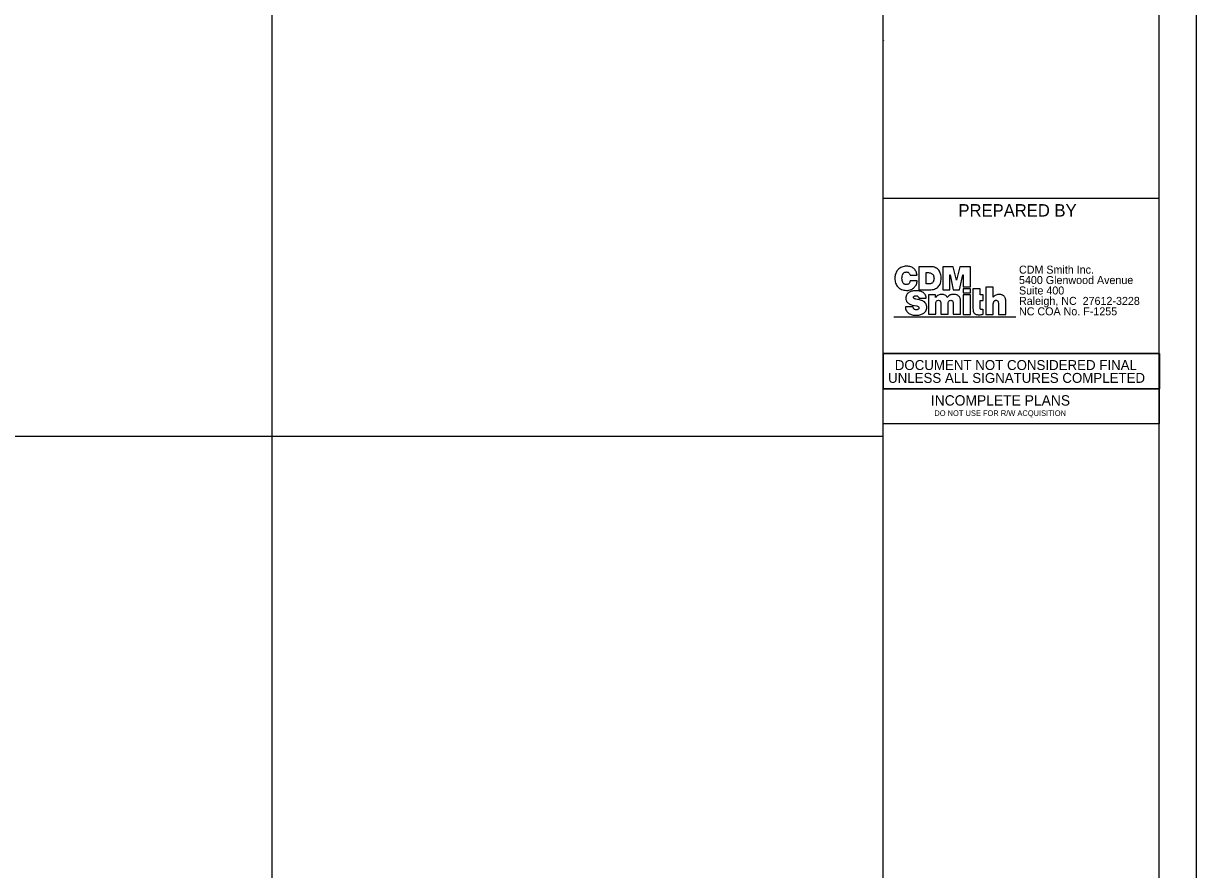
# Model space of a CAD drawing. Extents: x 0 to 1700, y -103 to 1100.
# Drawn here: x 1275 to 1700, y 498.6 to 805 of the extents above; entities that cross this region are included whole.
import ezdxf

# ---------------------------------------------------------------- set-up
doc = ezdxf.new("R2010")
doc.units = 0
for name, color, linetype in [('Default', 7, 'Continuous'), ('Level 17', 7, 'Continuous'), ('Sheet Block Title CELL', 7, 'Continuous'), ('Sheet Plan CELL', 7, 'Continuous'), ('Sheet_Plan_CELL', 7, 'Continuous')]:
    doc.layers.add(name, color=color, linetype=linetype)

msp = doc.modelspace()

# ---------------------------------------------------------------- linework, layer by layer
at = {"layer": 'Default'}
for p, q in [((1365, 1077.5), (1365, 22.52)), ((36.48, 655.5), (1586.48, 655.5))]:
    msp.add_line(p, q, dxfattribs=at)
at = {"layer": 'Level 17'}
msp.add_line((1699.98, 0.02), (1699.98, 1100), dxfattribs=at)
at = {"layer": 'Sheet Block Title CELL'}
msp.add_line((1590.33, 698.72), (1634.49, 698.71), dxfattribs=at)
for points in [[(1593.6, 711.17), (1593.52, 711.34), (1593.46, 711.51), (1593.34, 711.9), (1593.29, 712.3), (1593.26, 712.73), (1593.29, 713.15), (1593.34, 713.55), (1593.46, 713.95), (1593.52, 714.12), (1593.6, 714.29), (1593.71, 714.46), (1593.83, 714.6), (1593.94, 714.72), (1594.11, 714.83), (1594.25, 714.92), (1594.45, 714.97), (1594.65, 715), (1594.85, 715.03), (1595.05, 715), (1595.22, 714.97), (1595.36, 714.94), (1595.5, 714.89), (1595.65, 714.8), (1595.73, 714.72), (1595.9, 714.52), (1596.04, 714.32), (1596.13, 714.12), (1596.19, 713.92), (1596.21, 713.81), (1598.72, 713.81), (1598.66, 714.18), (1598.57, 714.55), (1598.49, 714.89), (1598.35, 715.2), (1598.2, 715.48), (1598.03, 715.77), (1597.83, 716.02), (1597.61, 716.22), (1597.35, 716.42), (1597.07, 716.62), (1596.78, 716.76), (1596.47, 716.88), (1596.1, 716.99), (1595.73, 717.05), (1595.33, 717.1), (1594.94, 717.1), (1594.45, 717.1), (1594, 717.02), (1593.57, 716.93), (1593.17, 716.79), (1592.81, 716.62), (1592.46, 716.42), (1592.12, 716.17), (1591.84, 715.91), (1591.58, 715.6), (1591.36, 715.29), (1591.16, 714.92), (1590.99, 714.52), (1590.84, 714.12), (1590.76, 713.67), (1590.7, 713.21), (1590.67, 712.73), (1590.7, 712.27), (1590.76, 711.82), (1590.84, 711.39), (1590.96, 711), (1591.13, 710.63), (1591.3, 710.26), (1591.53, 709.92), (1591.78, 709.6), (1592.07, 709.32), (1592.41, 709.09), (1592.75, 708.86), (1593.12, 708.69), (1593.52, 708.55), (1593.97, 708.44), (1594.42, 708.38), (1594.94, 708.35), (1595.36, 708.35), (1595.79, 708.44), (1596.19, 708.52), (1596.56, 708.67), (1596.9, 708.81), (1597.21, 709.01), (1597.49, 709.2), (1597.75, 709.46), (1597.98, 709.72), (1598.18, 709.97), (1598.35, 710.28), (1598.49, 710.57), (1598.6, 710.88), (1598.69, 711.19), (1598.74, 711.51), (1598.74, 711.82), (1596.21, 711.82), (1596.16, 711.53), (1596.07, 711.28), (1595.96, 711.05), (1595.82, 710.82), (1595.62, 710.65), (1595.42, 710.54), (1595.16, 710.46), (1594.85, 710.43), (1594.65, 710.46), (1594.45, 710.48), (1594.25, 710.54), (1594.11, 710.63), (1593.94, 710.74), (1593.83, 710.85), (1593.71, 711), (1593.6, 711.17)], [(1607.44, 712.27), (1607.44, 712.73), (1607.44, 713.13), (1607.41, 713.52), (1607.32, 713.92), (1607.24, 714.29), (1607.13, 714.63), (1606.98, 715), (1606.81, 715.31), (1606.61, 715.63), (1606.36, 715.91), (1606.1, 716.14), (1605.79, 716.37), (1605.45, 716.56), (1605.05, 716.71), (1604.63, 716.82), (1604.17, 716.88), (1603.66, 716.9), (1599.43, 716.91), (1599.43, 708.55), (1603.18, 708.55), (1603.69, 708.55), (1604.2, 708.61), (1604.65, 708.72), (1605.08, 708.84), (1605.45, 709.01), (1605.82, 709.2), (1606.13, 709.43), (1606.42, 709.69), (1606.64, 709.97), (1606.87, 710.28), (1607.04, 710.63), (1607.18, 710.99), (1607.3, 711.39), (1607.38, 711.82), (1607.44, 712.27)], [(1602.01, 714.77), (1602.84, 714.77), (1603.18, 714.75), (1603.46, 714.72), (1603.72, 714.63), (1603.94, 714.52), (1604.14, 714.4), (1604.31, 714.26), (1604.43, 714.12), (1604.54, 713.98), (1604.65, 713.81), (1604.71, 713.64), (1604.82, 713.3), (1604.85, 713.01), (1604.88, 712.78), (1604.85, 712.47), (1604.8, 712.13), (1604.71, 711.76), (1604.63, 711.59), (1604.54, 711.45), (1604.45, 711.28), (1604.31, 711.14), (1604.17, 711.02), (1604, 710.91), (1603.8, 710.82), (1603.57, 710.74), (1603.32, 710.71), (1603.03, 710.68), (1602.01, 710.68), (1602.01, 714.77)], [(1610.65, 713.92), (1610.71, 713.92), (1611.84, 708.55), (1614.12, 708.55), (1615.34, 713.92), (1615.39, 713.92), (1615.39, 709.6), (1618.04, 709.6), (1618.04, 716.9), (1614.23, 716.9), (1613.04, 711.99), (1613.01, 711.99), (1611.81, 716.9), (1608.04, 716.9), (1608.03, 708.55), (1610.65, 708.55), (1610.65, 713.92)], [(1602.21, 702.58), (1602.18, 702.81), (1602.12, 703.01), (1602.07, 703.24), (1601.98, 703.41), (1601.9, 703.58), (1601.78, 703.75), (1601.67, 703.89), (1601.39, 704.15), (1601.07, 704.37), (1600.76, 704.54), (1600.39, 704.69), (1600.02, 704.8), (1599.65, 704.89), (1598.91, 705.06), (1598.29, 705.17), (1598.03, 705.26), (1597.81, 705.34), (1597.69, 705.4), (1597.58, 705.48), (1597.49, 705.6), (1597.46, 705.77), (1597.49, 705.97), (1597.55, 706.11), (1597.64, 706.22), (1597.75, 706.31), (1597.89, 706.36), (1598.06, 706.39), (1598.37, 706.42), (1598.54, 706.39), (1598.72, 706.36), (1598.86, 706.28), (1599, 706.16), (1599.14, 706.05), (1599.25, 705.91), (1599.31, 705.74), (1599.34, 705.54), (1602.01, 705.54), (1601.98, 705.94), (1601.9, 706.28), (1601.78, 706.59), (1601.64, 706.87), (1601.44, 707.1), (1601.24, 707.33), (1601.02, 707.53), (1600.73, 707.67), (1600.48, 707.81), (1600.16, 707.93), (1599.88, 708.01), (1599.57, 708.1), (1599.23, 708.15), (1598.91, 708.18), (1598.29, 708.21), (1597.69, 708.18), (1597.38, 708.13), (1597.07, 708.1), (1596.75, 708.01), (1596.47, 707.93), (1596.19, 707.81), (1595.9, 707.67), (1595.65, 707.5), (1595.39, 707.3), (1595.19, 707.07), (1595.02, 706.85), (1594.88, 706.56), (1594.77, 706.25), (1594.68, 705.91), (1594.65, 705.51), (1594.68, 705.26), (1594.71, 705), (1594.77, 704.77), (1594.85, 704.55), (1594.94, 704.35), (1595.08, 704.15), (1595.22, 703.98), (1595.39, 703.81), (1595.59, 703.66), (1595.82, 703.52), (1596.07, 703.38), (1596.36, 703.27), (1596.67, 703.15), (1597.01, 703.04), (1597.81, 702.87), (1598.63, 702.7), (1598.91, 702.61), (1599.11, 702.53), (1599.25, 702.41), (1599.34, 702.3), (1599.4, 702.16), (1599.43, 701.99), (1599.4, 701.82), (1599.31, 701.68), (1599.2, 701.56), (1599.06, 701.48), (1598.91, 701.42), (1598.74, 701.36), (1598.43, 701.33), (1598.17, 701.36), (1597.95, 701.39), (1597.78, 701.48), (1597.64, 701.56), (1597.49, 701.73), (1597.38, 701.93), (1597.32, 702.1), (1597.29, 702.33), (1594.48, 702.33), (1594.51, 701.93), (1594.59, 701.56), (1594.71, 701.25), (1594.85, 700.94), (1595.02, 700.68), (1595.25, 700.42), (1595.48, 700.2), (1595.73, 700.03), (1596.02, 699.86), (1596.33, 699.71), (1596.64, 699.6), (1596.95, 699.52), (1597.29, 699.43), (1597.64, 699.4), (1597.98, 699.37), (1598.32, 699.35), (1599.03, 699.37), (1599.37, 699.43), (1599.71, 699.49), (1600.05, 699.57), (1600.36, 699.69), (1600.68, 699.8), (1600.96, 699.97), (1601.24, 700.14), (1601.47, 700.37), (1601.7, 700.6), (1601.87, 700.88), (1602.01, 701.19), (1602.12, 701.53), (1602.21, 701.9), (1602.21, 702.33), (1602.21, 702.58)], [(1605.56, 704), (1605.62, 704.2), (1605.73, 704.4), (1605.85, 704.54), (1605.99, 704.66), (1606.19, 704.74), (1606.44, 704.77), (1606.7, 704.74), (1606.93, 704.66), (1607.07, 704.54), (1607.18, 704.37), (1607.24, 704.18), (1607.3, 703.98), (1607.32, 703.75), (1607.32, 703.49), (1607.32, 699.69), (1610, 699.69), (1610, 703.49), (1610.02, 703.75), (1610.05, 704), (1610.11, 704.2), (1610.22, 704.4), (1610.34, 704.54), (1610.48, 704.66), (1610.68, 704.74), (1610.93, 704.77), (1611.19, 704.74), (1611.42, 704.66), (1611.56, 704.54), (1611.67, 704.37), (1611.73, 704.18), (1611.79, 703.98), (1611.81, 703.75), (1611.81, 703.49), (1611.81, 699.69), (1614.48, 699.69), (1614.48, 704.52), (1614.46, 704.94), (1614.43, 705.17), (1614.37, 705.37), (1614.31, 705.57), (1614.2, 705.77), (1614.09, 705.97), (1613.97, 706.14), (1613.8, 706.31), (1613.63, 706.45), (1613.43, 706.59), (1613.21, 706.7), (1612.98, 706.79), (1612.69, 706.85), (1612.41, 706.9), (1612.07, 706.9), (1611.76, 706.9), (1611.47, 706.87), (1611.22, 706.82), (1610.96, 706.76), (1610.76, 706.68), (1610.56, 706.59), (1610.25, 706.39), (1610.02, 706.19), (1609.85, 706.02), (1609.68, 705.79), (1609.51, 706.05), (1609.34, 706.28), (1609.11, 706.48), (1608.89, 706.62), (1608.6, 706.73), (1608.35, 706.85), (1608.06, 706.9), (1607.75, 706.9), (1607.41, 706.9), (1607.07, 706.85), (1606.76, 706.76), (1606.44, 706.65), (1606.16, 706.51), (1605.9, 706.31), (1605.68, 706.08), (1605.42, 705.76), (1605.42, 706.73), (1602.84, 706.73), (1602.83, 699.69), (1605.51, 699.69), (1605.51, 703.49), (1605.53, 703.75), (1605.56, 704)], [(1618.04, 708.89), (1615.39, 708.89), (1615.39, 707.44), (1618.04, 707.44), (1618.04, 708.89)], [(1618.04, 706.73), (1615.39, 706.73), (1615.39, 699.66), (1618.04, 699.66), (1618.04, 706.73)], [(1622.72, 706.73), (1621.56, 706.73), (1621.56, 708.89), (1618.95, 708.89), (1618.95, 706.73), (1618.95, 704.74), (1618.95, 702.27), (1618.95, 701.73), (1619, 701.25), (1619.09, 700.85), (1619.2, 700.51), (1619.34, 700.25), (1619.49, 700.05), (1619.68, 699.91), (1619.88, 699.77), (1620.14, 699.66), (1620.45, 699.57), (1620.82, 699.51), (1621.28, 699.51), (1621.59, 699.51), (1621.96, 699.57), (1622.36, 699.63), (1622.72, 699.74), (1622.72, 701.5), (1622.61, 701.48), (1622.41, 701.45), (1622.01, 701.42), (1621.87, 701.45), (1621.76, 701.53), (1621.7, 701.59), (1621.65, 701.65), (1621.62, 701.73), (1621.59, 701.87), (1621.56, 702.24), (1621.56, 704.74), (1622.72, 704.74), (1622.72, 706.73)], [(1630.77, 705.37), (1630.65, 705.62), (1630.57, 705.85), (1630.43, 706.05), (1630.28, 706.22), (1630.11, 706.39), (1629.94, 706.5), (1629.74, 706.62), (1629.52, 706.73), (1629.29, 706.79), (1629.06, 706.85), (1628.81, 706.87), (1628.55, 706.9), (1628.21, 706.87), (1627.9, 706.85), (1627.58, 706.79), (1627.24, 706.65), (1627.02, 706.5), (1626.82, 706.36), (1626.59, 706.16), (1626.36, 705.94), (1626.36, 709.52), (1623.63, 709.52), (1623.63, 699.66), (1626.36, 699.66), (1626.36, 703.07), (1626.36, 703.49), (1626.42, 703.89), (1626.53, 704.17), (1626.59, 704.29), (1626.65, 704.4), (1626.76, 704.54), (1626.93, 704.66), (1627.1, 704.74), (1627.27, 704.77), (1627.5, 704.77), (1627.67, 704.71), (1627.81, 704.63), (1627.95, 704.49), (1628.07, 704.35), (1628.12, 704.12), (1628.18, 703.86), (1628.18, 703.55), (1628.18, 699.66), (1630.91, 699.66), (1630.91, 704.15), (1630.91, 704.49), (1630.88, 704.8), (1630.82, 705.11), (1630.77, 705.37)]]:
    msp.add_lwpolyline(points, dxfattribs=at)
at = {"layer": 'Sheet Plan CELL'}
msp.add_circle((1586.47, 798.95), 0.0603, dxfattribs=at)
at = {"layer": 'Sheet_Plan_CELL'}
for p, q in [((1586.45, 88.91), (1586.48, 1077.5)), ((1686.45, 22.52), (1686.48, 1077.5)), ((1686.45, 741.63), (1586.45, 741.63)), ((1686.51, 685.43), (1586.51, 685.43))]:
    msp.add_line(p, q, dxfattribs=at)
for points in [[(1586.51, 685.43), (1686.51, 685.43), (1686.51, 672.7), (1586.51, 672.7)], [(1586.47, 672.7), (1686.47, 672.7), (1686.47, 659.96), (1586.47, 659.96)]]:
    msp.add_lwpolyline(points, close=True, dxfattribs=at)

# ---------------------------------------------------------------- texts
at = {"layer": 'Sheet Block Title CELL'}
for s, height, p in [('CDM Smith Inc.', 2.9003, (1635.66, 714.41)), ('5400 Glenwood Avenue', 2.9003, (1635.66, 710.64)), ('Suite 400', 2.9, (1635.66, 706.86)), ('Raleigh, NC  27612-3228', 2.9003, (1635.66, 703.09)), ('NC COA No. F-1255', 2.9003, (1635.66, 699.31))]:
    msp.add_text(s, height=height, rotation=359.9982, dxfattribs=at).set_placement(p)
at = {"layer": 'Sheet_Plan_CELL'}
for s, height, p in [('PREPARED BY', 4.5, (1613.73, 735.08)), ('DOCUMENT NOT CONSIDERED FINAL', 3.6, (1590.66, 679.51)), ('UNLESS ALL SIGNATURES COMPLETED', 3.6, (1588.23, 674.85))]:
    msp.add_text(s, height=height, rotation=0, dxfattribs=at).set_placement(p)
for s, height, p in [('INCOMPLETE PLANS', 3.75, (1603.73, 666.63)), ('DO NOT USE FOR R/W ACQUISITION', 2.025, (1605, 662.86))]:
    msp.add_text(s, height=height, dxfattribs=at).set_placement(p)

doc.saveas('drawing.dxf')
